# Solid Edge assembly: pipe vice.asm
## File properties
Author: Deepak Maini
Template: normal.asm
Last saved by: MYPC
Revision: 6
Application: Solid Edge
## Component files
base.par
Screw.par
moveable jaw.par
handle.par
handle screw.par
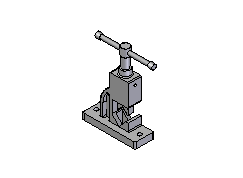
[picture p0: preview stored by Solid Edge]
